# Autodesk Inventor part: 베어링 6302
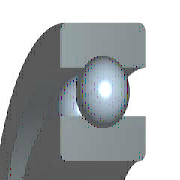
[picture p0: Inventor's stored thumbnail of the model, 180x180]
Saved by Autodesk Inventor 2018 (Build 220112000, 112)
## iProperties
IsCustomPart: 1
Created: 2012-02
Part Number: 베어링 6302
Material: 강철, 연강
Document SubType Name: Modeling
Standard: JIS B 1521
Designer: mdu-01
Standards Organization: JIS
Language: ko-KR
Size Designation: 6302 15x42x13
Categories: <MemberInstance><Categories><Category DisplayName="샤프트 부품" InternalName="7f7aeb1f-a693-4053-b835-cee3144e0d98" Mnemonic="SHFT"><Category DisplayName="베어링" Inter
Density: 1 g/cm^3
Appearance: 노란색
Author: mdu-01
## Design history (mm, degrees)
sketch "스케치" dims "d0" = 7.02 (= -0.26 x WD + 0.26 x BD)
  geometry: L1 (2.99, 14.25)-(10.01, 14.25); L2 (6.5, 14.25)-(6.5, 10.74); L3 (6.5, 14.25)-(6.5, 17.76); L4 (3.892, 11.901)-(0, 11.901); L5 (0, 7.5)-(13, 7.5); L6 (3.892, 16.599)-(0, 16.599); L7 (0, 21)-(13, 21); L8 (13, 7.5)-(13, 11.901); L9 (9.108, 11.901)-(13, 11.901); L10 (9.108, 16.599)-(13, 16.599); L11 (13, 21)-(13, 16.599); L12 (-1.4, 0)-(8.4, 0) reference; L13 (0, -0.3)-(0, 5.3) reference
  constraints: 22 end point, 4 point on line, 2 collinear, 2 perpendicular, 2 symmetric about line, 1 midpoint, 1 parallel, 14 other
  dimensions: "d9" = 15 diameter of L5 L12 (= WD); "d11" = 42 diameter of L7 L12 (= BD); "d12" = 13 distance between parallel lines of L8 L13 (= KB); "d13" = 23.802 diameter of L9 L12 (= 0.326 x BD + 0.674 x WD)
revolve "본체" stored, may be unused: angle "d6" = 90 deg
revolve "볼" stored, may be unused: angle "d7" = 90 deg
pattern_circular "IDS_ARRAYBALL[SIMPL:T]" dims angle "d3" = 360 deg
body "Solid1"
fillet "모깎기1" dims "d1" = 1 (= KRS)
other parameters: "WD" = 15 [user parameter; used in 5 equation terms], "BD" = 42 [user parameter; used in 5 equation terms], "KB" = 13 [user parameter; used in 1 equation term], "KRS" = 1 [user parameter; used in 1 equation term], "d4" = 0, "d5" = 0, "d8" = 0, "d14" = 0, "d15" = 0, "BBA" = 0 [user parameter], "BC0" = 5400000 [user parameter], "BC" = 1.14e+07 [user parameter], "BR" = 21 (= 0.5 x BD) [user parameter], "WR" = 7.5 (= 0.5 x WD) [user parameter]
